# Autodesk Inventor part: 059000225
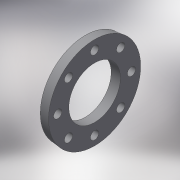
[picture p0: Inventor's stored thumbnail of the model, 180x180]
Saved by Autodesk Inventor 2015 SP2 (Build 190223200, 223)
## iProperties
Created: 2017-10
Part Number: 059000225
Material: Generic
Description: PLASSON BACKING FLANGE PVC 225
Document SubType Name: Modeling
Designer: KIM
Density: 1 g/cm^3
Appearance: Default
Author: KIM
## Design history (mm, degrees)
derived "059000.ipt"
feature "Solid1::059000.ipt"
tag "TaggingFeature1"
body "Solid1"
other parameters: "d0" = 32, "d1" = 243, "d3" = 333.2, "d5" = 22, "d6" = 147.5, "d7" = 32, "d8" = 0, "d10" = 360 deg, "D_" = 225, "E_" = 243, "H_" = 32, "Dp_" = 295, "S_" = 22
